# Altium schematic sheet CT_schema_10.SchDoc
size 274 x 160 mm
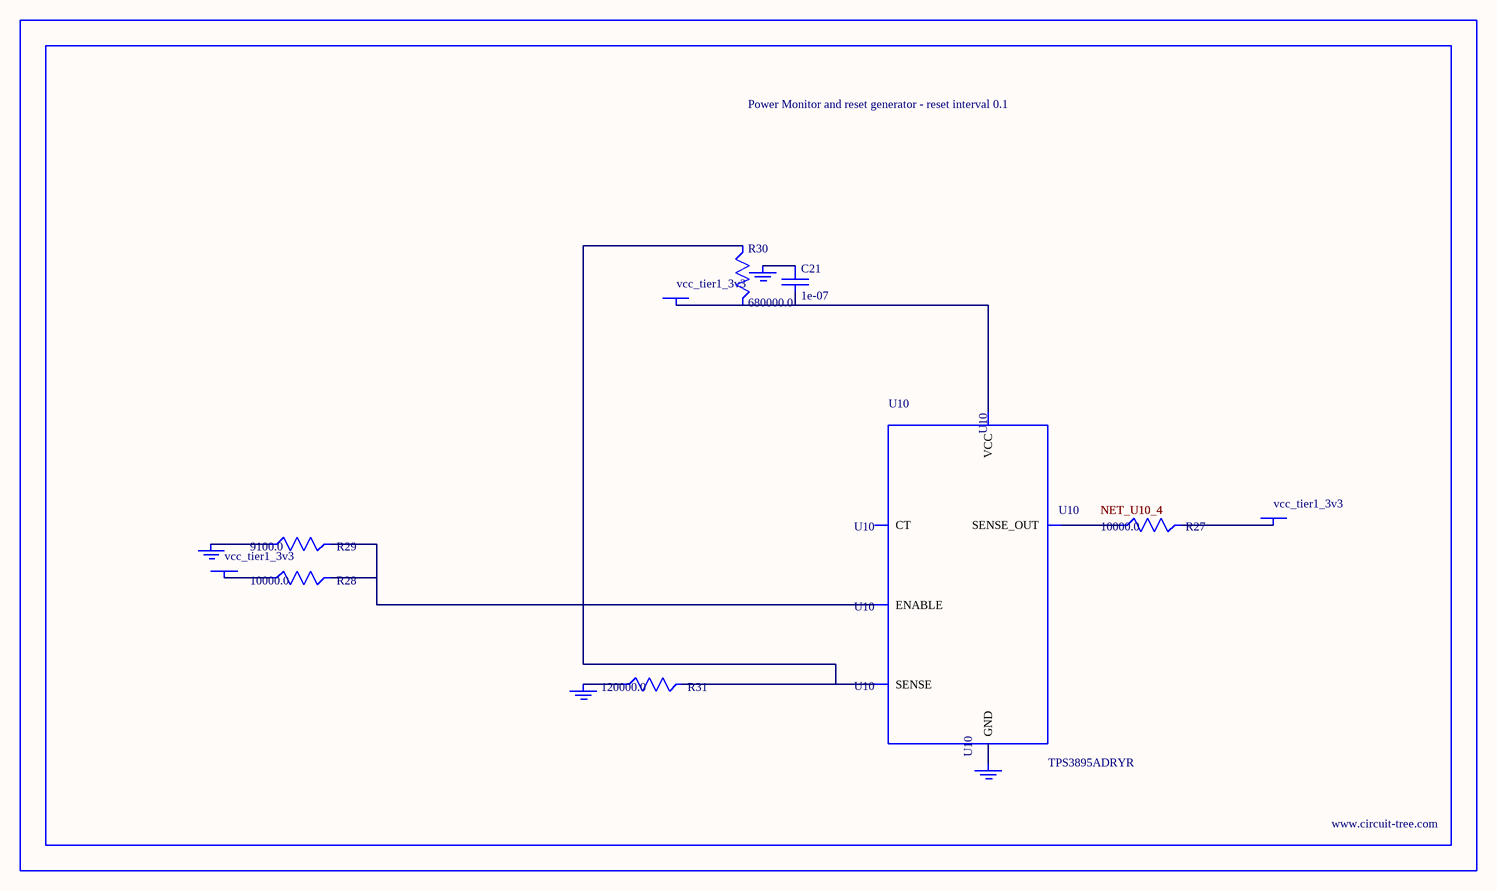
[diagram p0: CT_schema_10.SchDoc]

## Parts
BORDER9  (no value)
C21  1e-07  [C0402]
GND_INSTANCE_9_0  (no value)
GND_INSTANCE_9_1  (no value)
GND_INSTANCE_9_2  (no value)
GND_INSTANCE_9_3  (no value)
POWER_INSTANCE_9_0  vcc_tier1_3v3
POWER_INSTANCE_9_1  vcc_tier1_3v3
POWER_INSTANCE_9_2  vcc_tier1_3v3
R27  10000.0  [R0603]
R28  10000.0  [R0603]
R29  9100.0  [R0603]
R30  680000.0  [R0603]
R31  120000.0  [R0603]
U10  TPS3895ADRYR  [SON-6]

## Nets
NetC21_1: C21.1 GND_INSTANCE_9_2.0(GND)
NetC21_2: C21.2 POWER_INSTANCE_9_2.0(PWR) R30.2 U10.6(VCC)
NetGND_INSTANCE_9_0_0: GND_INSTANCE_9_0.0(GND) R29.1
NetGND_INSTANCE_9_1_0: GND_INSTANCE_9_1.0(GND) R31.1
NetGND_INSTANCE_9_3_0: GND_INSTANCE_9_3.0(GND) U10.2(GND)
NetPOWER_INSTANCE_9_0_0: POWER_INSTANCE_9_0.0(PWR) R28.1
NetPOWER_INSTANCE_9_1_0: POWER_INSTANCE_9_1.0(PWR) R27.2
NetR27_1: R27.1 U10.4(SENSE_OUT)
NetR28_2: R28.2 R29.2 U10.1(ENABLE)
NetR30_1: R30.1 R31.2 U10.3(SENSE)

Not connected (* = marked no-connect by the designer): U10 5(CT)

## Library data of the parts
BORDER9 = BORDER_PAGE9
C21 = C0402C104K3RACTU
GND_INSTANCE_9_0-GND_INSTANCE_9_3 = GND
POWER_INSTANCE_9_0-POWER_INSTANCE_9_2 = PWR
R27 R28 = RC0603JR-0710KL
R29 = RC0603JR-079K1L
R30 = RC0603JR-07680KL
R31 = RC0603JR-07120KL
